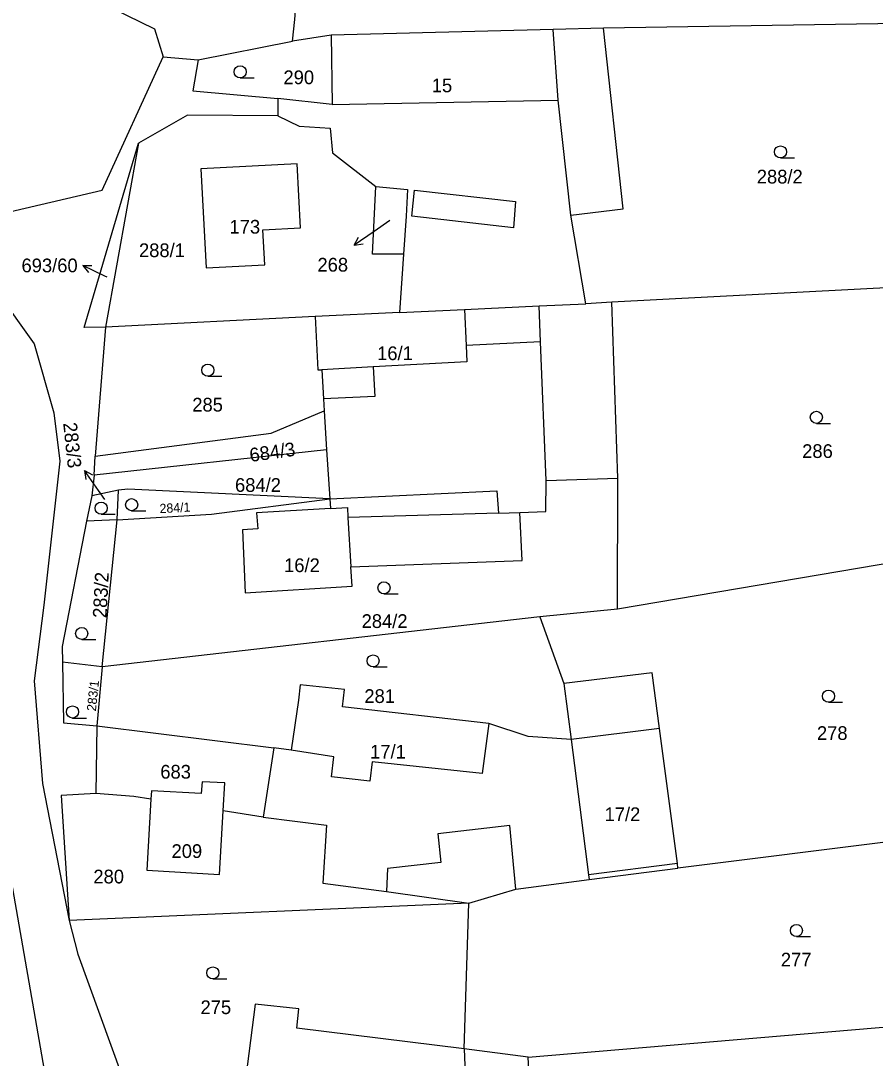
# Model space of a CAD drawing. Extents: x -747333 to -743907, y -1134120 to -1130051.
# Drawn here: x -746246 to -746140.1, y -1132212.3 to -1132083.8 of the extents above; entities that cross this region are included whole.
import ezdxf

# ---------------------------------------------------------------- set-up
doc = ezdxf.new("R2010")
doc.units = 0
for name, color, linetype in [('Hranice parcel', 7, 'Continuous'), ('Parcelní čísla', 7, 'Continuous'), ('Pop  PČ popisy', 7, 'Continuous'), ('Vnitřní kresba', 7, 'Continuous'), ('Značky kultur', 7, 'Continuous')]:
    doc.layers.add(name, color=color, linetype=linetype)

msp = doc.modelspace()

# ---------------------------------------------------------------- linework, layer by layer
at = {"layer": 'Hranice parcel'}
for p, q in [((-746124.88, -1132083.93), (-746173.78, -1132084.7)), ((-746207.51, -1132085.56), (-746212.3, -1132086.3)), ((-746223.98, -1132088.61), (-746212.3, -1132086.3)), ((-746228.31, -1132088.24), (-746223.98, -1132088.61)), ((-746214.11, -1132093.4), (-746214.11, -1132095.55)), ((-746231.38, -1132098.93), (-746235.45, -1132121.74)), ((-746198.55, -1132112.69), (-746199.05, -1132119.92)), ((-746121.77, -1132115.99), (-746172.76, -1132118.66)), ((-746172.76, -1132118.66), (-746176, -1132118.86)), ((-746172, -1132140.43), (-746172.76, -1132118.66)), ((-746209.52, -1132120.42), (-746235.45, -1132121.74)), ((-746199.05, -1132119.92), (-746209.52, -1132120.42)), ((-746235.45, -1132121.74), (-746236.75, -1132137.7)), ((-746208.49, -1132130.62), (-746208.4, -1132132.08)), ((-746208.4, -1132132.08), (-746208.09, -1132136.95)), ((-746208.09, -1132136.95), (-746236.89, -1132140.06)), ((-746208.09, -1132136.95), (-746207.7, -1132143.01)), ((-746236.89, -1132140.06), (-746236.75, -1132137.7)), ((-746236.89, -1132140.06), (-746237.17, -1132142.63)), ((-746172.05, -1132156.68), (-746172, -1132140.43)), ((-746233.85, -1132141.94), (-746237.17, -1132142.63)), ((-746234.03, -1132145.62), (-746233.85, -1132141.94)), ((-746237.17, -1132142.63), (-746237.82, -1132145.77)), ((-746207.7, -1132143.01), (-746207.62, -1132144.2)), ((-746234.03, -1132145.62), (-746237.82, -1132145.77)), ((-746235.89, -1132163.82), (-746234.03, -1132145.62)), ((-746117.65, -1132147.46), (-746172.05, -1132156.68)), ((-746172.05, -1132156.68), (-746181.68, -1132157.61)), ((-746181.68, -1132157.61), (-746235.89, -1132163.82)), ((-746181.68, -1132157.61), (-746178.69, -1132165.88)), ((-746235.89, -1132163.82), (-746240.81, -1132163.25)), ((-746235.89, -1132163.82), (-746236.54, -1132171.13)), ((-746167.75, -1132164.54), (-746178.69, -1132165.88)), ((-746178.69, -1132165.88), (-746177.8, -1132172.8)), ((-746236.54, -1132171.13), (-746236.67, -1132179.5)), ((-746236.54, -1132171.13), (-746214.63, -1132173.86)), ((-746214.63, -1132173.86), (-746215.94, -1132182.42)), ((-746215.94, -1132182.42), (-746220.9, -1132181.63)), ((-746113.11, -1132182.3), (-746164.58, -1132188.76)), ((-746175.57, -1132190.17), (-746164.58, -1132188.76)), ((-746190.47, -1132193.09), (-746239.96, -1132195.24)), ((-746191.06, -1132211.13), (-746190.47, -1132193.09)), ((-746183.12, -1132212.16), (-746110.33, -1132206.03)), ((-746183.12, -1132212.16), (-746191.06, -1132211.13)), ((-746182.52, -1132224.41), (-746183.12, -1132212.16))]:
    msp.add_line(p, q, dxfattribs=at)
for points in [[(-746230.47, -1132050.07), (-746232.13, -1132058.95), (-746238.55, -1132074.67), (-746241.1, -1132073.85), (-746243.03, -1132079.01), (-746234.55, -1132082.27), (-746229.39, -1132084.77), (-746228.31, -1132088.24)], [(-746212.3, -1132086.3), (-746212.01, -1132083.63), (-746210.13, -1132057.3)], [(-746173.78, -1132084.7), (-746180.02, -1132084.87), (-746207.51, -1132085.56)], [(-746176, -1132118.86), (-746177.85, -1132107.87), (-746171.35, -1132107.07), (-746173.78, -1132084.7)], [(-746207.51, -1132085.56), (-746207.39, -1132094.17), (-746214.11, -1132093.4)], [(-746258.07, -1132105.71), (-746253.04, -1132108.76), (-746235.88, -1132104.76), (-746228.31, -1132088.24)], [(-746223.98, -1132088.61), (-746224.66, -1132092.46), (-746214.11, -1132093.4)], [(-746214.11, -1132095.55), (-746225.32, -1132095.47), (-746231.38, -1132098.93)], [(-746214.11, -1132095.55), (-746211.5, -1132096.85), (-746207.66, -1132097.08), (-746207.35, -1132100.16), (-746201.98, -1132104.3)], [(-746235.45, -1132121.74), (-746238.12, -1132121.77), (-746231.38, -1132098.93)], [(-746223.65, -1132102.13), (-746223.02, -1132114.4), (-746215.74, -1132114.03), (-746215.98, -1132109.68), (-746211.33, -1132109.44), (-746211.74, -1132101.52), (-746223.65, -1132102.13)], [(-746198.55, -1132112.69), (-746202.42, -1132112.7), (-746201.98, -1132104.3)], [(-746201.98, -1132104.3), (-746198.06, -1132104.69), (-746198.22, -1132107.99), (-746198.55, -1132112.69)], [(-746248.97, -1132117.3), (-746244.31, -1132123.79), (-746241.88, -1132132.35), (-746241.11, -1132138.34), (-746243.12, -1132156.17), (-746244.31, -1132165.56), (-746243.27, -1132178.27), (-746239.96, -1132195.24)], [(-746199.05, -1132119.92), (-746191.02, -1132119.53), (-746181.76, -1132119.09), (-746176, -1132118.86)], [(-746209.52, -1132120.42), (-746209.18, -1132127.04), (-746208.68, -1132127.01), (-746208.49, -1132130.62)], [(-746236.75, -1132137.7), (-746214.96, -1132134.88), (-746208.4, -1132132.08)], [(-746184.17, -1132144.7), (-746180.95, -1132144.55), (-746180.89, -1132140.74), (-746172, -1132140.43)], [(-746207.7, -1132143.01), (-746232.7, -1132141.79), (-746233.85, -1132141.94)], [(-746207.7, -1132143.01), (-746187.01, -1132142.02), (-746186.78, -1132144.78), (-746184.17, -1132144.7)], [(-746234.03, -1132145.62), (-746222.33, -1132144.91), (-746207.7, -1132143.01)], [(-746207.62, -1132144.2), (-746216.76, -1132144.74), (-746216.62, -1132146.72), (-746218.5, -1132146.85), (-746218.18, -1132154.65), (-746204.93, -1132153.84)], [(-746204.93, -1132153.84), (-746205.08, -1132151.41), (-746183.86, -1132150.62), (-746184.17, -1132144.7)], [(-746237.82, -1132145.77), (-746240.84, -1132161.3), (-746240.81, -1132163.25)], [(-746240.81, -1132163.25), (-746240.67, -1132170.74), (-746236.54, -1132171.13)], [(-746164.58, -1132188.76), (-746164.65, -1132188.17), (-746166.85, -1132171.43), (-746167.75, -1132164.54)], [(-746177.8, -1132172.8), (-746183.14, -1132172.44), (-746188.01, -1132170.82), (-746206.13, -1132168.75), (-746205.87, -1132166.6), (-746211.35, -1132166.06), (-746211.56, -1132167.94), (-746212.47, -1132174.13), (-746214.63, -1132173.86)], [(-746177.8, -1132172.8), (-746175.65, -1132189.58), (-746175.57, -1132190.17)], [(-746239.72, -1132225.13), (-746242.13, -1132218.98), (-746247.56, -1132187.7), (-746250.26, -1132174.19)], [(-746220.9, -1132181.63), (-746220.71, -1132178.2), (-746223.51, -1132178.05), (-746223.6, -1132179.52), (-746229.78, -1132179.17), (-746229.84, -1132180.22)], [(-746236.67, -1132179.5), (-746240.97, -1132179.73), (-746239.96, -1132195.24)], [(-746229.84, -1132180.22), (-746231.98, -1132179.88), (-746236.67, -1132179.5)], [(-746229.84, -1132180.22), (-746230.33, -1132189), (-746221.34, -1132189.53), (-746220.9, -1132181.63)], [(-746215.94, -1132182.42), (-746208.11, -1132183.41), (-746208.57, -1132190.63), (-746200.66, -1132191.63), (-746190.47, -1132193.09)], [(-746190.47, -1132193.09), (-746184.66, -1132191.35), (-746175.57, -1132190.17)], [(-746239.96, -1132195.24), (-746238.89, -1132199.39), (-746233.44, -1132214.44), (-746228.44, -1132218.67)], [(-746191.06, -1132211.13), (-746211.76, -1132208.57), (-746211.51, -1132206.18), (-746216.94, -1132205.61), (-746218.08, -1132214.58), (-746228.44, -1132218.67)]]:
    msp.add_lwpolyline(points, dxfattribs=at)
at = {"layer": 'Pop  PČ popisy'}
for p, q in [((-746200.27, -1132108.52), (-746202.2, -1132109.87)), ((-746202.2, -1132109.87), (-746204.658, -1132111.591)), ((-746204.658, -1132111.591), (-746204.125, -1132110.607)), ((-746204.658, -1132111.591), (-746203.551, -1132111.427)), ((-746238.267, -1132114.094), (-746237.148, -1132114.083)), ((-746235.57, -1132115.41), (-746238.267, -1132114.094)), ((-746238.267, -1132114.094), (-746237.587, -1132114.984)), ((-746235.27, -1132115.56), (-746235.57, -1132115.41)), ((-746236.35, -1132141.95), (-746238.071, -1132139.492)), ((-746238.071, -1132139.492), (-746237.087, -1132140.025)), ((-746238.071, -1132139.492), (-746237.907, -1132140.599)), ((-746235.56, -1132143.09), (-746236.35, -1132141.95))]:
    msp.add_line(p, q, dxfattribs=at)
at = {"layer": 'Vnitřní kresba'}
for p, q in [((-746179.42, -1132093.6), (-746180.02, -1132084.87)), ((-746207.39, -1132094.17), (-746179.42, -1132093.6)), ((-746177.85, -1132107.87), (-746179.42, -1132093.6)), ((-746197.53, -1132107.99), (-746197.22, -1132104.76)), ((-746197.22, -1132104.76), (-746184.71, -1132106.15)), ((-746184.71, -1132106.15), (-746184.94, -1132109.45)), ((-746184.94, -1132109.45), (-746197.53, -1132107.99)), ((-746181.58, -1132123.55), (-746181.76, -1132119.09)), ((-746191.02, -1132119.53), (-746190.81, -1132123.99)), ((-746181.58, -1132123.55), (-746190.81, -1132123.99)), ((-746190.81, -1132123.99), (-746190.71, -1132126.03)), ((-746180.89, -1132140.74), (-746181.58, -1132123.55)), ((-746202.31, -1132126.66), (-746208.68, -1132127.01)), ((-746190.71, -1132126.03), (-746202.31, -1132126.66)), ((-746202.31, -1132126.66), (-746202.11, -1132130.33)), ((-746202.11, -1132130.33), (-746208.49, -1132130.62)), ((-746207.62, -1132144.2), (-746205.51, -1132144.07)), ((-746205.51, -1132144.07), (-746205.44, -1132145.33)), ((-746186.78, -1132144.78), (-746205.44, -1132145.33)), ((-746205.44, -1132145.33), (-746205.08, -1132151.41)), ((-746188.01, -1132170.82), (-746188.84, -1132177.04)), ((-746166.85, -1132171.43), (-746177.8, -1132172.8)), ((-746207.19, -1132174.96), (-746212.47, -1132174.13)), ((-746207.5, -1132177.42), (-746207.19, -1132174.96)), ((-746202.43, -1132175.58), (-746202.74, -1132177.96)), ((-746188.84, -1132177.04), (-746202.43, -1132175.58)), ((-746202.74, -1132177.96), (-746207.5, -1132177.42)), ((-746185.39, -1132183.48), (-746194.33, -1132184.5)), ((-746184.66, -1132191.35), (-746185.39, -1132183.48)), ((-746194.33, -1132184.5), (-746193.92, -1132188.06)), ((-746200.54, -1132188.81), (-746200.66, -1132191.63)), ((-746193.92, -1132188.06), (-746200.54, -1132188.81)), ((-746164.65, -1132188.17), (-746175.65, -1132189.58)), ((-746191.06, -1132211.13), (-746190.75, -1132218.16))]:
    msp.add_line(p, q, dxfattribs=at)
at = {"layer": 'Značky kultur'}
for p, q in [((-746218.793, -1132090.86), (-746217.043, -1132090.86)), ((-746151.883, -1132100.78), (-746150.133, -1132100.78)), ((-746222.793, -1132127.81), (-746221.043, -1132127.81)), ((-746147.433, -1132133.65), (-746145.683, -1132133.65)), ((-746236.003, -1132144.91), (-746234.253, -1132144.91)), ((-746232.233, -1132144.48), (-746230.483, -1132144.48)), ((-746200.983, -1132154.77), (-746199.233, -1132154.77)), ((-746238.413, -1132160.42), (-746236.663, -1132160.42)), ((-746202.333, -1132163.83), (-746200.583, -1132163.83)), ((-746145.933, -1132168.2), (-746144.183, -1132168.2)), ((-746239.553, -1132170.15), (-746237.803, -1132170.15)), ((-746149.903, -1132197.23), (-746148.153, -1132197.23)), ((-746222.173, -1132202.48), (-746220.423, -1132202.48))]:
    msp.add_line(p, q, dxfattribs=at)
for centre in [(-746218.793, -1132090.11), (-746151.883, -1132100.03), (-746222.793, -1132127.06), (-746147.433, -1132132.9), (-746236.003, -1132144.16), (-746232.233, -1132143.73), (-746200.983, -1132154.02), (-746238.413, -1132159.67), (-746202.333, -1132163.08), (-746145.933, -1132167.45), (-746239.553, -1132169.4), (-746149.903, -1132196.48), (-746222.173, -1132201.73)]:
    msp.add_circle(centre, 0.75, dxfattribs=at)

# ---------------------------------------------------------------- texts
at = {"layer": 'Parcelní čísla'}
for s, p in [('290', (-746213.43, -1132091.64)), ('15', (-746195.06, -1132092.64)), ('288/2', (-746154.81, -1132103.94)), ('173', (-746220.11, -1132110.15)), ('288/1', (-746231.32, -1132113.06)), ('693/60', (-746245.871, -1132114.94)), ('268', (-746209.219, -1132114.853)), ('16/1', (-746201.83, -1132125.82)), ('285', (-746224.72, -1132132.19)), ('286', (-746149.19, -1132137.94)), ('684/2', (-746219.43, -1132142.14)), ('16/2', (-746213.35, -1132152.08)), ('284/2', (-746203.75, -1132159)), ('281', (-746203.41, -1132168.29)), ('278', (-746147.36, -1132172.87)), ('17/1', (-746202.7, -1132175.18)), ('683', (-746228.68, -1132177.66)), ('17/2', (-746173.66, -1132182.92)), ('209', (-746227.29, -1132187.49)), ('280', (-746236.97, -1132190.64)), ('277', (-746151.83, -1132200.93)), ('275', (-746223.7, -1132206.83))]:
    msp.add_text(s, height=1.7, dxfattribs=at).set_placement(p)
for s, height, rotation, p in [('283/3', 1.7, 276, (-746240.715, -1132133.612)), ('684/3', 1.7, 8, (-746217.511, -1132138.441)), ('284/1', 1.14, 3, (-746228.74, -1132144.779)), ('283/2', 1.7, 87, (-746235.351, -1132157.804)), ('283/1', 1.14, 84, (-746236.663, -1132169.349))]:
    msp.add_text(s, height=height, rotation=rotation, dxfattribs=at).set_placement(p)

doc.saveas('drawing.dxf')
